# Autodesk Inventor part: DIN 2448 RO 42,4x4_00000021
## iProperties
Created: 2006-02
Part Number: DIN 2448 RO 42,4x4_00000021
Material: Default
Document SubType Name: Modeling
Designer: FranzK
Stock Number: DIN 2448 RO 42,4x4
Mass: 437.343 g
Surface Area: 2193.46 cm^2
Volume: 437.343 cm^3
Density: 1 g/cm^3
G_L: 894.000 mm
G_W: 42.400 mm
G_H: 42.400 mm
AFG_Item: 42.4 x 4
CSToolsMass: 0.4
CSToolsVolume: 437343.0
CSToolsArea: 2193.0
Author: FranzK
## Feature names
1. AFG_Detailed_DIN 2448 RO 42,4x4_00000021 [Extrusion]
2. AFG_Simplified_DIN 2448 RO 42,4x4_00000021 [Extrusion]
3. Extrusion5
